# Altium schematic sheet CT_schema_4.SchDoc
size 372 x 328 mm
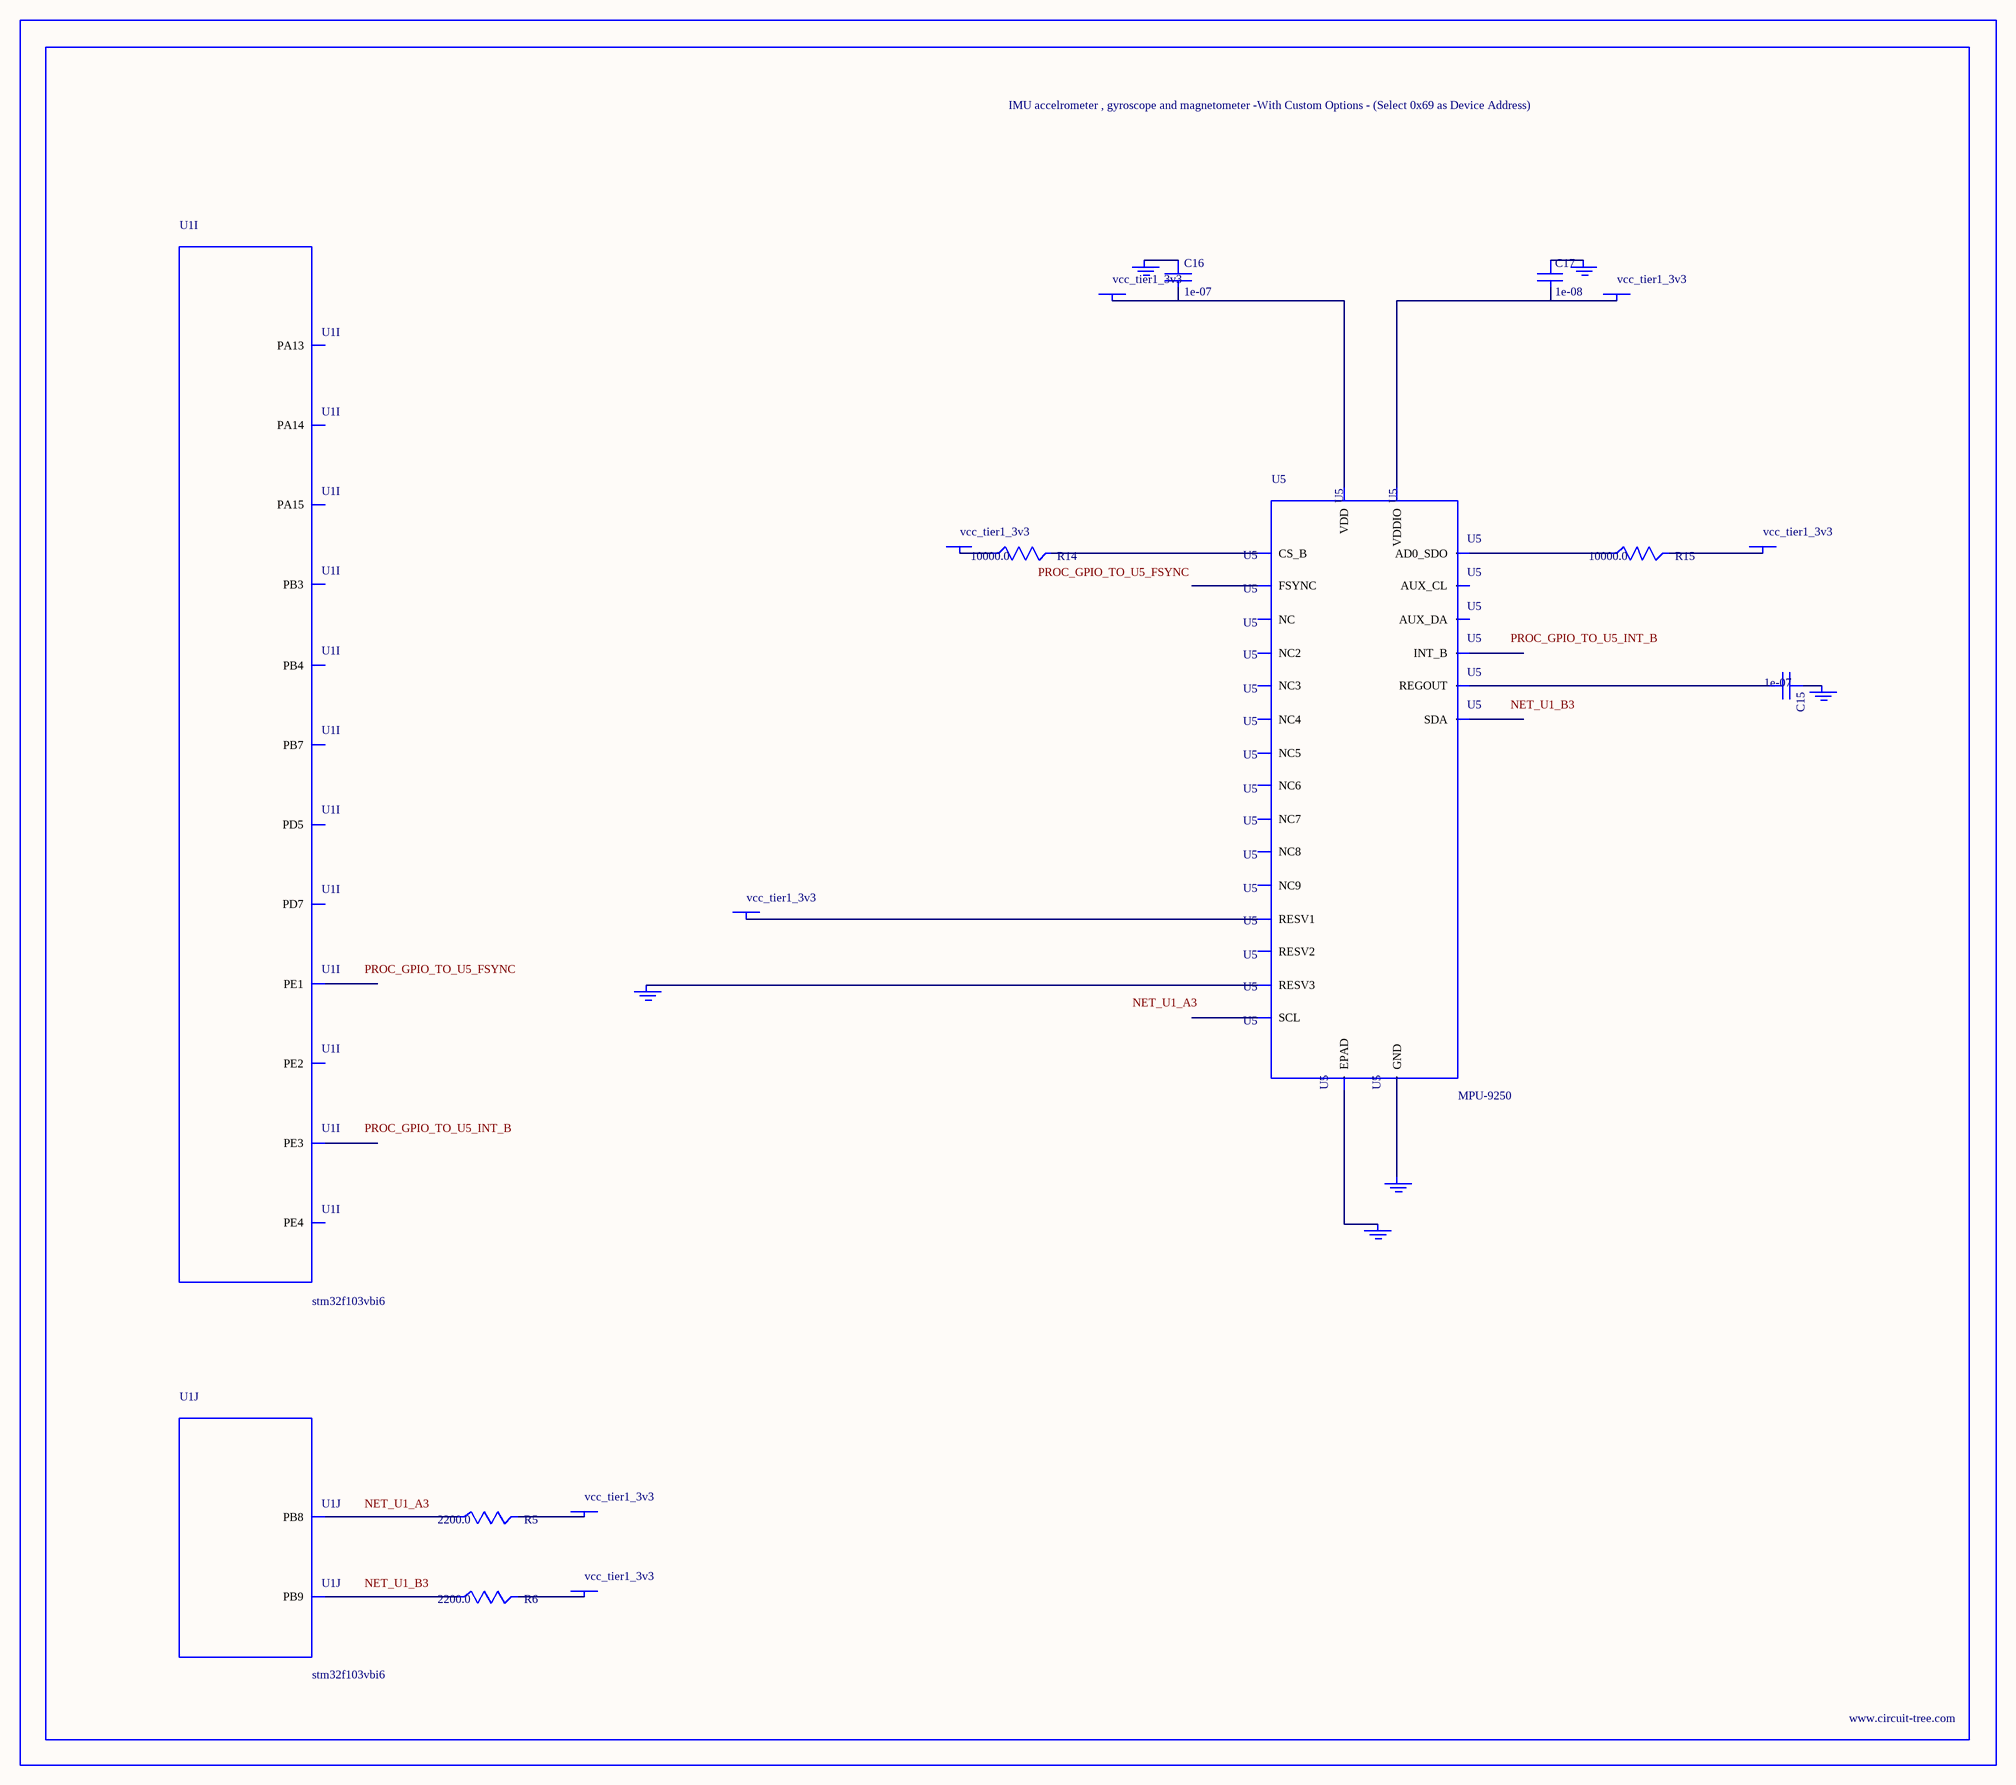
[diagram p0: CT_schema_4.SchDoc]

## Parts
BORDER3  (no value)
C15  1e-07  [C0402]
C16  1e-07  [C0402]
C17  1e-08  [C0402]
GND_INSTANCE_3_0  (no value)
GND_INSTANCE_3_1  (no value)
GND_INSTANCE_3_2  (no value)
GND_INSTANCE_3_3  (no value)
GND_INSTANCE_3_4  (no value)
GND_INSTANCE_3_5  (no value)
POWER_INSTANCE_3_0  vcc_tier1_3v3
POWER_INSTANCE_3_1  vcc_tier1_3v3
POWER_INSTANCE_3_2  vcc_tier1_3v3
POWER_INSTANCE_3_3  vcc_tier1_3v3
POWER_INSTANCE_3_4  vcc_tier1_3v3
POWER_INSTANCE_3_5  vcc_tier1_3v3
POWER_INSTANCE_3_6  vcc_tier1_3v3
R5  2200.0  [R0603]
R6  2200.0  [R0603]
R14  10000.0  [R0603]
R15  10000.0  [R0603]
U1  stm32f103vbi6  [UFBGA100]  (parts I,J of 10)
U5  MPU-9250  [QFN24_2]

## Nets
NetC15_1: C15.1 GND_INSTANCE_3_1.0(GND)
NetC15_2: C15.2 U5.10(REGOUT)
NetC16_1: C16.1 GND_INSTANCE_3_2.0(GND)
NetC16_2: C16.2 POWER_INSTANCE_3_3.0(PWR) U5.13(VDD)
NetC17_1: C17.1 GND_INSTANCE_3_0.0(GND)
NetC17_2: C17.2 POWER_INSTANCE_3_1.0(PWR) U5.8(VDDIO)
NetGND_INSTANCE_3_3_0: GND_INSTANCE_3_3.0(GND) U5.20(RESV3)
NetGND_INSTANCE_3_4_0: GND_INSTANCE_3_4.0(GND) U5.25(EPAD)
NetGND_INSTANCE_3_5_0: GND_INSTANCE_3_5.0(GND) U5.18(GND)
NetPOWER_INSTANCE_3_0_0: POWER_INSTANCE_3_0.0(PWR) U5.1(RESV1)
NetPOWER_INSTANCE_3_2_0: POWER_INSTANCE_3_2.0(PWR) R15.2
NetPOWER_INSTANCE_3_4_0: POWER_INSTANCE_3_4.0(PWR) R14.1
NetPOWER_INSTANCE_3_5_0: POWER_INSTANCE_3_5.0(PWR) R5.2
NetPOWER_INSTANCE_3_6_0: POWER_INSTANCE_3_6.0(PWR) R6.2
NetR5_1: R5.1 U1.A3(PB8)
NetR6_1: R6.1 U1.B3(PB9)
NetR14_2: R14.2 U5.22(CS_B)
NetR15_1: R15.1 U5.9(AD0_SDO)

Not connected (* = marked no-connect by the designer): U1 A1(PE3) A2(PE1) A5(PD7) A6(PD5) A7(PB4) A8(PB3) A9(PA15) A10(PA14) A11(PA13) B1(PE4) B2(PE2) B4(PB7); U5 2(NC) 3(NC2) 4(NC3) 5(NC4) 6(NC5) 7(AUX_CL) 11(FSYNC) 12(INT_B) 14(NC6) 15(NC7) 16(NC8) 17(NC9) 19(RESV2) 21(AUX_DA) 23(SCL) 24(SDA)

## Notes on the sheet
- Labels drawn without touching a wire or pin: NET_U1_A3, NET_U1_B3, PROC_GPIO_TO_U5_FSYNC, PROC_GPIO_TO_U5_INT_B

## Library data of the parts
BORDER3 = BORDER_PAGE3
C15 C16 = C0402C104K3RACTU
C17 = C0402C103K3RAC
GND_INSTANCE_3_0-GND_INSTANCE_3_5 = GND
POWER_INSTANCE_3_0-POWER_INSTANCE_3_6 = PWR
R5 R6 = RC0603JR-072K2L
R14 R15 = RC0603JR-0710KL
